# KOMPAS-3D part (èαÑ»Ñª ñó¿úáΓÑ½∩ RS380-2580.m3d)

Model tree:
1. Эскиз:1
2. Операция выдавливания:1
     Расстояние 1 = 3
3. Эскиз:2
4. Операция выдавливания:2
     Расстояние 1 = 25
5. Фаска:1
     Угол = 45; Длина 1 = 1; Длина 2 = 1
